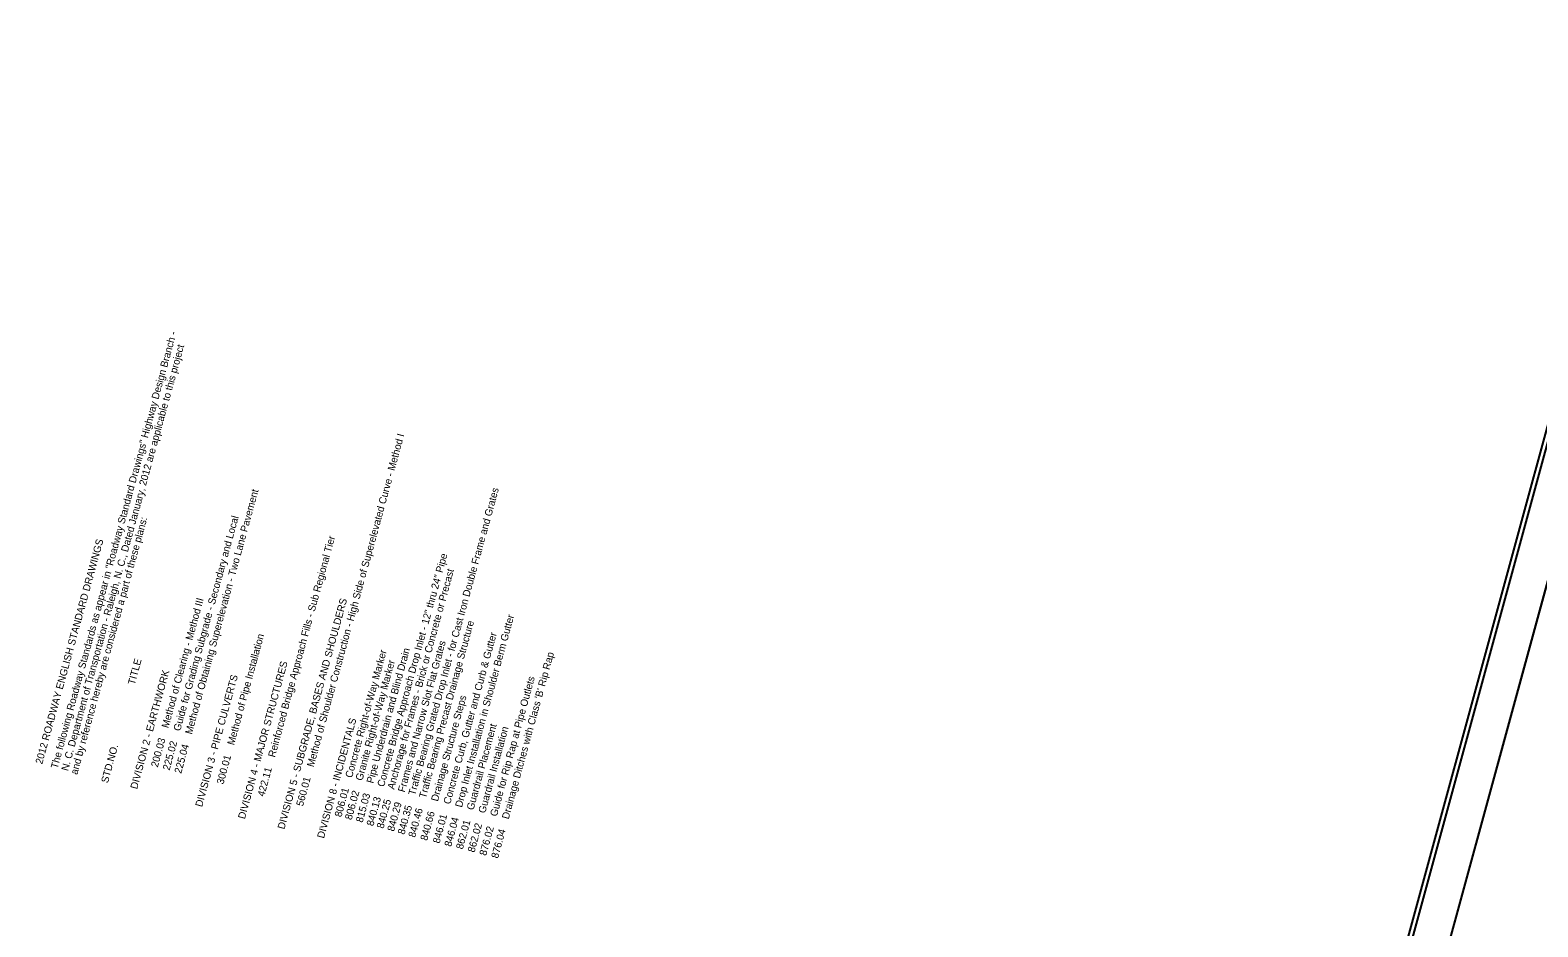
# Model space of a CAD drawing. Extents: x 2076126 to 2079903, y 925480 to 928006.
# Drawn here: x 2076620 to 2077447, y 926895 to 927387 of the extents above; entities that cross this region are included whole.
import ezdxf

# ---------------------------------------------------------------- set-up
doc = ezdxf.new("R2010")
doc.units = 0
for name, color, linetype in [('Default', 7, 'Continuous'), ('Sheet Cutting Line CELL', 7, 'Continuous'), ('Sheet Plan CELL', 7, 'Continuous'), ('Sheet Plot Border Inside CELL', 7, 'Continuous'), ('Sheet Plot Border Outside CELL', 7, 'Continuous')]:
    doc.layers.add(name, color=color, linetype=linetype)

msp = doc.modelspace()

# ---------------------------------------------------------------- linework, layer by layer
at = {"layer": 'Sheet Cutting Line CELL'}
msp.add_line((2077182.3, 926093.56), (2077625.3, 927717.73), dxfattribs=at)
at = {"layer": 'Sheet Plan CELL'}
msp.add_lwpolyline([(2076586.13, 927983.55), (2076191.41, 926536.41), (2077204.41, 926260.12), (2077599.12, 927707.25)], close=True, dxfattribs=at)
at = {"layer": 'Sheet Plot Border Inside CELL'}
msp.add_lwpolyline([(2077166.43, 926111.37), (2077604.82, 927718.65), (2076587, 927996.27), (2076148.61, 926388.98)], close=True, dxfattribs=at)
at = {"layer": 'Sheet Plot Border Outside CELL'}
msp.add_lwpolyline([(2077182.3, 926093.56), (2077625.3, 927717.73), (2076568.89, 928005.87), (2076125.89, 926381.7)], close=True, dxfattribs=at)

# ---------------------------------------------------------------- texts
at = {"layer": 'Default'}
for s, height, p in [('The following Roadway Standards as appear in "Roadway Standard Drawings" Highway Design Branch -', 4, (2076634.85, 926981.75)), ('N. C. Department of Transportation - Raleigh, N. C., Dated January, 2012 are applicable to this project', 3.99997, (2076640.6, 926980.51)), ('560.01    Method of Shoulder Construction - High Side of Superelevated Curve - Method I', 4, (2076769.51, 926961.13)), ('225.04    Method of Obtaining Superelevation - Two Lane Pavement', 4, (2076702.69, 926979.08)), ('840.35    Traffic Bearing Grated Drop Inlet - for Cast Iron Double Frame and Grates', 4, (2076825.22, 926945.56)), ('and by reference hereby are considered a part of these plans:', 4, (2076645.63, 926978.48)), ('225.02    Guide for Grading Subgrade - Secondary and Local', 4, (2076696.27, 926980.84)), ('422.11    Reinforced Bridge Approach Fills - Sub Regional Tier', 4, (2076748.24, 926966.44)), ('2012 ROADWAY ENGLISH STANDARD DRAWINGS', 4, (2076626.41, 926984.22)), ('840.13    Concrete Bridge Approach Drop Inlet - 12" thru 24" Pipe ', 4, (2076808.12, 926950.22)), ('840.25    Anchorage for Frames - Brick or Concrete or Precast', 4, (2076813.67, 926948.87)), ('200.03    Method of Clearing - Method III', 4, (2076689.81, 926982.52)), ('DIVISION 5 - SUBGRADE, BASES AND SHOULDERS', 4, (2076759.31, 926948.47)), ('840.46    Traffic Bearing Precast Drainage Structure', 4, (2076831.07, 926943.96)), ('846.04    Drop Inlet Installation in Shoulder Berm Gutter', 4, (2076850.86, 926938.94)), ('300.01    Method of Pipe Installation ', 4, (2076725.84, 926973.15)), ('840.29    Frames and Narrow Slot Flat Grates', 4, (2076819.49, 926947.29)), ('846.01    Concrete Curb, Gutter and Curb & Gutter', 4, (2076844.44, 926940.69)), ('806.01    Concrete Right-of-Way Marker', 4, (2076790.57, 926955.18)), ('815.03    Pipe Underdrain and Blind Drain', 4, (2076802.24, 926952.16)), ("876.04    Drainage Ditches with Class 'B' Rip Rap", 4, (2076876.56, 926932.5)), ('STD.NO.                       TITLE', 4, (2076662.47, 926973.88)), ('DIVISION 2 - EARTHWORK', 4, (2076678.5, 926970.51)), ('DIVISION 4 - MAJOR STRUCTURES', 4, (2076737.62, 926954.1)), ('806.02    Granite Right-of-Way Marker', 4, (2076796.23, 926953.63)), ('DIVISION 3 - PIPE CULVERTS', 4, (2076714.15, 926960.73)), ('876.02    Guide for Rip Rap at Pipe Outlets', 4, (2076870.06, 926933.99)), ('840.66    Drainage Structure Steps', 4, (2076837.67, 926942.25)), ('DIVISION 8 - INCIDENTALS', 4, (2076781, 926943.49)), ('862.01    Guardrail Placement', 4, (2076857.21, 926937.49)), ('862.02    Guardrail Installation', 4, (2076863.61, 926935.75))]:
    msp.add_text(s, height=height, rotation=74.7434, dxfattribs=at).set_placement(p)

doc.saveas('drawing.dxf')
